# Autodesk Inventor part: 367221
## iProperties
Created: 2006-08
Part Number: 367221
Material: 8.8 vz
Description: Zylinderschraube
Vendor: Autodesk Inc.
Document SubType Name: Modeling
Standard: DIN 912
Designer: I.Baliuc
Standards Organization: DIN
Language: de-DE
Size Designation: M6 x 16
Categories: <MemberInstance Version="R10.0.0"><Categories><Category DisplayName="Schrauben" InternalName="e4da775c-781d-43d5-af7c-5136215cf5a6" Mnemonic="FSTN"><Category Di
Density: 7.85 g/cm^3
Mass: 6.58508 g
Surface Area: 6.89507 cm^2
Volume: 0.838863 cm^3
Abmessung: M6 x 16
Author: T.Messerschmitt
Comments: DIN 912 - M6 x 16
Revision Number: 367221
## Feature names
1. Körper [Revolution]
2. Loch [Extrusion]
3. Rundung1 [Fillet]
4. Fase1 [Chamfer]
